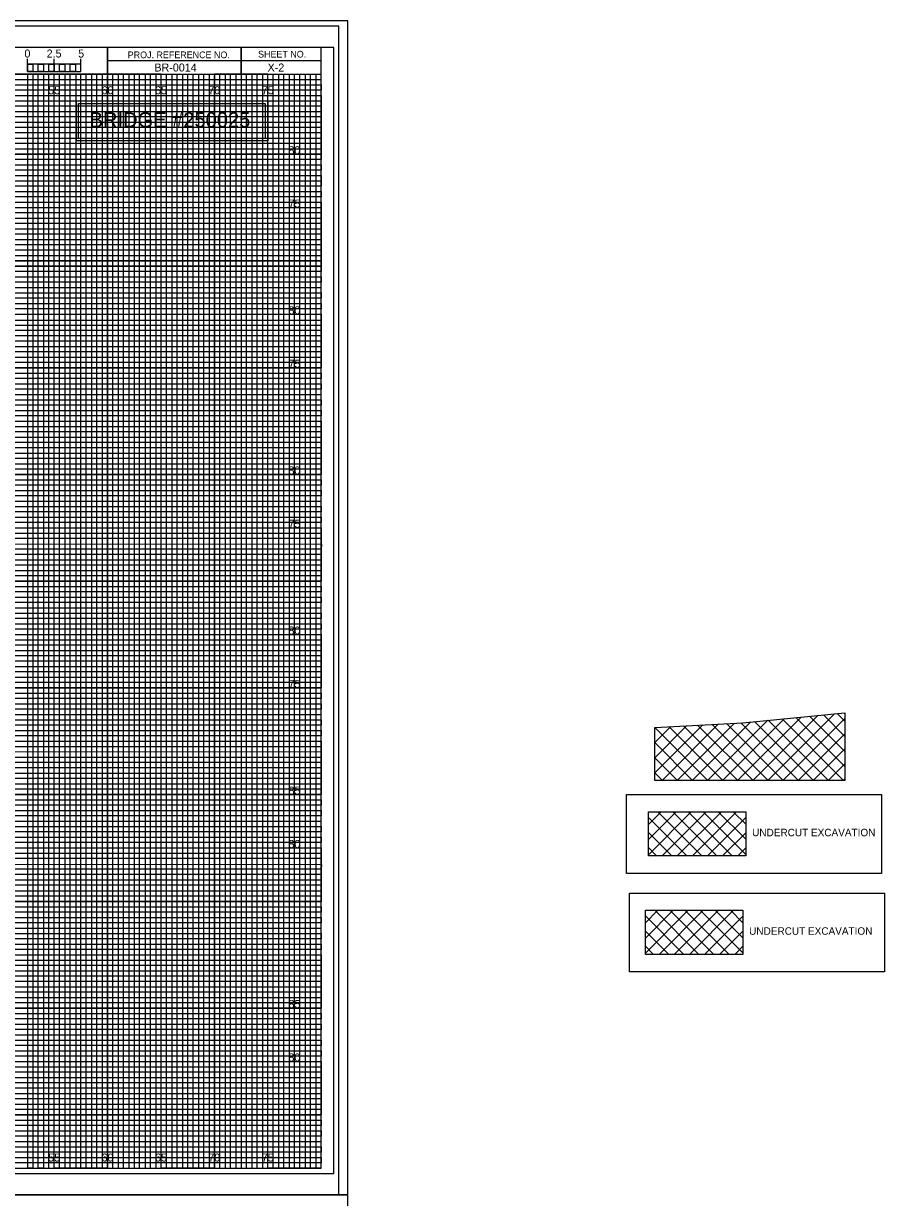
# Model space of a CAD drawing. Extents: x -8 to 533, y -20 to 768.
# Drawn here: x 132.1 to 212.8, y 107.2 to 217.2 of the extents above; entities that cross this region are included whole.
import ezdxf

# ---------------------------------------------------------------- set-up
doc = ezdxf.new("R2010")
doc.units = 0
for name, color, linetype in [('Old_Level_1', 7, 'Continuous'), ('Old_Level_34', 7, 'Continuous'), ('Prop Grid Mask', 7, 'Continuous'), ('Prop XS Bar Scale Labels', 7, 'Continuous'), ('Prop XS Elevation Labels', 7, 'Continuous'), ('Prop XS Offset Labels', 7, 'Continuous'), ('Prop XS Project Number', 7, 'Continuous'), ('Prop XS Sheet Number', 7, 'Continuous'), ('Prop XS Side Slope Text', 7, 'Continuous'), ('Prop XS Undercut Exc', 7, 'Continuous'), ('Sheet Cross Section CELL', 7, 'Continuous'), ('Sheet Cross Section Grid Major CELL', 7, 'Continuous'), ('Sheet Cross Section Grid Middle CELL', 7, 'Continuous'), ('Sheet Cross Section Grid Minor 1 CELL', 7, 'Continuous'), ('Sheet Cross Section Grid Minor 2 CELL', 7, 'Continuous'), ('Sheet Cross Section Scale CELL', 7, 'Continuous'), ('Sheet Cutting Line CELL', 7, 'Continuous'), ('Sheet DOT Grid CELL', 7, 'Continuous'), ('Sheet Plot Border Inside CELL', 7, 'Continuous'), ('Sheet Plot Border Outside CELL', 7, 'Continuous'), ('WEI Plot Border', 7, 'Continuous')]:
    doc.layers.add(name, color=color, linetype=linetype)

msp = doc.modelspace()

# ---------------------------------------------------------------- linework, layer by layer
at = {"layer": 'Old_Level_34'}
msp.add_lwpolyline([(137.26, 209.75), (154.74, 209.75), (154.74, 206.46), (137.26, 206.46)], close=True, dxfattribs=at)
at = {"layer": 'Prop Grid Mask'}
for points in [[(137.08, 210), (155, 210), (155, 206.24), (137.08, 206.24)], [(188.59, 145), (212.47, 145), (212.47, 137.61), (188.59, 137.61)], [(188.87, 135.78), (212.76, 135.78), (212.76, 128.39), (188.87, 128.39)]]:
    msp.add_lwpolyline(points, close=True, dxfattribs=at)
at = {"layer": 'Prop XS Undercut Exc'}
for p, q in [((194.76, 146.33), (200.25, 151.81)), ((196.18, 146.33), (201.82, 151.97)), ((197.59, 146.33), (203.38, 152.12)), ((199, 146.33), (204.95, 152.27)), ((200.42, 146.33), (206.52, 152.42)), ((200.58, 151.85), (206.11, 146.33)), ((201.83, 146.33), (208.08, 152.57)), ((201.87, 151.97), (207.52, 146.33)), ((203.16, 152.1), (208.93, 146.33)), ((203.25, 146.33), (209.05, 152.13)), ((204.45, 152.22), (209.05, 147.62)), ((205.74, 152.35), (209.05, 149.04)), ((207.03, 152.47), (209.05, 150.45)), ((208.32, 152.6), (209.05, 151.87)), ((191.24, 147.05), (195.73, 151.54)), ((191.24, 148.46), (194.23, 151.45)), ((191.24, 149.88), (192.74, 151.37)), ((191.24, 151.29), (196.21, 146.33)), ((191.93, 146.33), (197.22, 151.62)), ((192.58, 151.36), (197.62, 146.33)), ((193.35, 146.33), (198.72, 151.7)), ((193.92, 151.44), (199.03, 146.33)), ((195.26, 151.51), (200.45, 146.33)), ((196.61, 151.58), (201.86, 146.33)), ((197.95, 151.66), (203.28, 146.33)), ((199.29, 151.73), (204.69, 146.33)), ((204.66, 146.33), (209.05, 150.71)), ((191.24, 149.88), (194.79, 146.33)), ((206.08, 146.33), (209.05, 149.3)), ((191.24, 148.46), (193.38, 146.33)), ((207.49, 146.33), (209.05, 147.89)), ((191.24, 147.05), (191.96, 146.33)), ((208.9, 146.33), (209.05, 146.47)), ((190.64, 139.37), (194.65, 143.38)), ((190.64, 140.79), (193.24, 143.38)), ((190.64, 142.2), (191.83, 143.38)), ((191.53, 143.38), (195.66, 139.26)), ((191.94, 139.26), (196.07, 143.38)), ((192.94, 143.38), (197.07, 139.26)), ((193.35, 139.26), (197.48, 143.38)), ((194.36, 143.38), (198.49, 139.26)), ((194.77, 139.26), (198.9, 143.38)), ((195.77, 143.38), (199.76, 139.39)), ((197.19, 143.38), (199.76, 140.81)), ((198.6, 143.38), (199.76, 142.22)), ((190.64, 142.86), (194.24, 139.26)), ((196.18, 139.26), (199.76, 142.84)), ((190.64, 141.44), (192.83, 139.26)), ((197.6, 139.26), (199.76, 141.42)), ((190.64, 140.03), (191.42, 139.26)), ((199.01, 139.26), (199.76, 140.01)), ((190.36, 130.15), (194.37, 134.16)), ((190.36, 131.56), (192.96, 134.16)), ((190.36, 132.98), (191.54, 134.16)), ((190.36, 133.63), (193.96, 130.03)), ((191.25, 134.16), (195.37, 130.03)), ((191.66, 130.03), (195.79, 134.16)), ((192.66, 134.16), (196.79, 130.03)), ((193.07, 130.03), (197.2, 134.16)), ((194.07, 134.16), (198.2, 130.03)), ((194.49, 130.03), (198.61, 134.16)), ((195.49, 134.16), (199.48, 130.17)), ((195.9, 130.03), (199.48, 133.61)), ((196.9, 134.16), (199.48, 131.58)), ((198.32, 134.16), (199.48, 133)), ((190.36, 132.22), (192.55, 130.03)), ((197.31, 130.03), (199.48, 132.2)), ((190.36, 130.81), (191.13, 130.03)), ((198.73, 130.03), (199.48, 130.79))]:
    msp.add_line(p, q, dxfattribs=at)
for points in [[(209.05, 152.67), (209.05, 146.33), (191.24, 146.33), (191.24, 151.29), (199.48, 151.74)], [(190.64, 143.38), (199.76, 143.38), (199.76, 139.26), (190.64, 139.26)], [(190.36, 134.16), (199.48, 134.16), (199.48, 130.03), (190.36, 130.03)]]:
    msp.add_lwpolyline(points, close=True, dxfattribs=at)
at = {"layer": 'Sheet Cross Section CELL'}
for p, q in [((152.5, 215), (152.5, 212.5)), ((152.5, 212.5), (152.5, 215)), ((160, 213.75), (140, 213.75)), ((140, 213.75), (140, 212.5)), ((140, 212.5), (160, 212.5))]:
    msp.add_line(p, q, dxfattribs=at)
for points in [[(160, 215), (0, 215), (0, 110), (160, 110)], [(140, 215), (130, 215), (130, 212.52), (140, 212.52)], [(160, 215), (140, 215), (140, 212.5), (160, 212.5)]]:
    msp.add_lwpolyline(points, close=True, dxfattribs=at)
at = {"layer": 'Sheet Cross Section Grid Major CELL'}
for p, q in [((135, 110), (135, 212.5)), ((145, 212.5), (140, 212.5)), ((140, 212.5), (140, 110)), ((145, 110), (145, 212.5)), ((155, 212.5), (150, 212.5)), ((150, 212.5), (150, 110)), ((155, 110), (155, 212.5)), ((140, 110), (135, 110)), ((150, 110), (145, 110)), ((160, 110), (155, 110)), ((160, 110), (160, 110))]:
    msp.add_line(p, q, dxfattribs=at)
for points in [[(0, 210), (160, 210), (160, 205), (0, 205)], [(0, 200), (160, 200), (160, 195), (0, 195)], [(0, 190), (160, 190), (160, 185), (0, 185)], [(0, 180), (160, 180), (160, 175), (0, 175)], [(0, 170), (160, 170), (160, 165), (0, 165)], [(0, 160), (160, 160), (160, 155), (0, 155)], [(0, 150), (160, 150), (160, 145), (0, 145)], [(0, 140), (160, 140), (160, 135), (0, 135)], [(0, 130), (160, 130), (160, 125), (0, 125)], [(0, 120), (160, 120), (160, 115), (0, 115)]]:
    msp.add_lwpolyline(points, dxfattribs=at)
at = {"layer": 'Sheet Cross Section Grid Middle CELL'}
for points in [[(0, 212.5), (137.5, 212.5)], [(130, 212.5), (132.5, 212.5), (132.5, 110), (137.5, 110), (137.5, 212.5), (142.5, 212.5), (142.5, 110), (147.5, 110), (147.5, 212.5), (152.5, 212.5), (152.5, 110), (157.5, 110), (157.5, 212.5)], [(0, 202.5), (160, 202.5), (160, 207.5), (0, 207.5)], [(0, 192.5), (160, 192.5), (160, 197.5), (0, 197.5)], [(0, 182.5), (160, 182.5), (160, 187.5), (0, 187.5)], [(0, 172.5), (160, 172.5), (160, 177.5), (0, 177.5)], [(0, 162.5), (160, 162.5), (160, 167.5), (0, 167.5)], [(0, 152.5), (160, 152.5), (160, 157.5), (0, 157.5)], [(0, 142.5), (160, 142.5), (160, 147.5), (0, 147.5)], [(0, 132.5), (160, 132.5), (160, 137.5), (0, 137.5)], [(0, 122.5), (160, 122.5), (160, 127.5), (0, 127.5)], [(0, 112.5), (160, 112.5), (160, 117.5), (0, 117.5)]]:
    msp.add_lwpolyline(points, dxfattribs=at)
at = {"layer": 'Sheet Cross Section Grid Minor 1 CELL'}
msp.add_line((0, 212), (160, 212), dxfattribs=at)
for points in [[(0, 211.5), (135, 211.5), (160, 211.5), (160, 211), (0, 211)], [(0, 210.5), (160, 210.5), (160, 209.5), (0, 209.5)], [(0, 209), (160, 209), (160, 208.5), (0, 208.49)], [(0, 208), (160, 208), (160, 207), (0, 207)], [(0, 206.5), (160, 206.5), (160, 206), (0, 206)], [(0, 205.5), (160, 205.5), (160, 204.5), (0, 204.5)], [(0, 204), (160, 204), (160, 203.5), (0, 203.5)], [(0, 203), (160, 203), (160, 202), (0, 202)], [(0, 201.5), (160, 201.5), (160, 201), (0, 201)], [(0, 200.5), (160, 200.5), (160, 199.5), (0, 199.5)], [(0, 199), (160, 199), (160, 198.5), (0, 198.5)], [(0, 198), (160, 198), (160, 196.97), (160, 196.5), (160, 196), (0, 196)], [(0, 197), (160, 197), (160, 196.5), (0, 196.5)], [(0, 195.5), (160, 195.5), (160, 194.5), (0, 194.52)], [(0, 194.52), (160, 194.5), (160, 194), (0, 194)], [(0, 193.5), (160, 193.5), (160, 193), (0, 193)], [(0, 192), (160, 192), (160, 191.5), (0, 191.5)], [(0, 191), (160, 191), (160, 190.5), (0, 190.5)], [(-0.04, 189.44), (160, 189.44), (160, 188.94), (-0.04, 188.94)], [(0, 188.5), (160, 188.5), (160, 188), (0, 188)], [(0, 187), (160, 187), (160, 186.5), (0, 186.5)], [(0, 186), (160, 186), (160, 185.5), (0, 185.5)], [(0, 184.5), (160, 184.5), (160, 184), (0, 184)], [(0, 183.5), (160, 183.5), (160, 183), (0, 183)], [(0, 182), (160, 182), (160, 181.5), (0, 181.5)], [(0, 181), (160, 181), (160, 180.5), (0, 180.5)], [(0, 179.5), (160, 179.5), (160, 178.99), (0, 179)], [(0, 178.5), (160, 178.5), (160, 178), (0, 178)], [(0, 177), (160, 177), (160, 176.5), (0, 176.5)], [(0, 176), (160, 176), (160, 175.5), (0, 175.5)], [(0, 174.5), (160, 174.5), (160, 174), (0, 174)], [(0, 173.5), (160, 173.5), (160, 173), (0, 173)], [(0, 172), (160, 172), (160, 171.5), (0, 171.5)], [(0, 171), (160, 171), (160, 170.5), (0, 170.5)], [(0, 169.5), (160, 169.5), (160, 169), (0, 169)], [(0, 168.5), (160.03, 168.46), (160, 168), (0, 168)], [(0, 167), (160, 167), (160, 166.5), (0, 166.5)], [(0, 166), (160, 166), (160, 165.5), (0, 165.5)], [(0, 164.5), (160, 164.5), (160, 164), (0, 164)], [(0, 163.5), (160, 163.5), (160, 163), (0, 163)], [(0, 162), (160, 162), (160, 161.5), (0, 161.5)], [(0, 161), (160, 161), (160, 160.5), (0, 160.5)], [(0, 159.5), (160, 159.5), (160, 159), (0, 159)], [(0, 158.5), (160, 158.5), (160, 158), (0, 158)], [(0, 157), (160, 157), (160, 156.5), (0, 156.5)], [(0, 156), (160, 156), (160, 155.5), (0, 155.5)], [(0, 154.5), (160, 154.5), (160, 154), (0, 154)], [(0, 153.5), (160, 153.5), (160, 153), (0, 153)], [(0, 152), (160, 152), (160, 151.5), (0, 151.5)], [(0, 151), (160, 151), (160, 150.5), (0, 150.5)], [(0, 149.5), (160, 149.5), (160, 148.99), (0, 149)], [(0, 148.5), (160, 148.5), (160, 148), (0, 148)], [(0, 147), (160, 147), (160, 146.5), (0, 146.5)], [(0, 146), (160, 146), (160, 145.5), (0, 145.5)], [(0, 144.5), (160, 144.5), (160, 144), (0, 144)], [(0, 143.5), (160, 143.5), (160, 143), (0, 143)], [(0, 142), (160, 142), (160, 141.5), (0, 141.5)], [(0, 141), (160, 141), (160, 140.5), (0, 140.5)], [(0, 139.5), (160, 139.5), (160, 139), (0, 139)], [(0, 138.5), (160.03, 138.46), (160, 138), (0, 138)], [(0, 137), (160, 137), (160, 136.5), (0, 136.5)], [(0, 136), (160, 136), (160, 135.5), (0, 135.5)], [(0, 134.5), (160, 134.5), (160, 134), (0, 134)], [(0, 133.5), (160, 133.5), (160, 133), (0, 133)], [(0, 132), (160, 132), (160, 131.5), (0, 131.5)], [(0, 131), (160, 131), (160, 130.5), (0, 130.5)], [(0, 129.5), (160, 129.5), (160, 129), (0, 129)], [(0, 128.5), (160, 128.5), (160, 128), (0, 128)], [(0, 127), (160, 127), (160, 126.5), (0, 126.5)], [(0, 126), (160, 126), (160, 125.5), (0, 125.5)], [(0, 124.5), (160, 124.5), (160, 124), (0, 124)], [(0, 123.5), (160, 123.5), (160, 123), (0, 123)], [(0, 122), (160, 122), (160, 121.5), (0, 121.5)], [(0, 121), (160, 121), (160, 120.5), (0, 120.5)], [(0, 119.5), (160, 119.5), (160, 119), (0, 119)], [(0, 118.5), (160, 118.5), (160, 118), (0, 118)], [(0, 117), (160, 117), (160, 116.5), (0, 116.5)], [(0, 116), (160, 116), (160, 115.5), (0, 115.5)], [(0, 114.5), (160, 114.5), (160, 114), (0, 114)], [(0, 113.5), (160, 113.5), (160, 113), (0, 113)], [(0, 112), (160, 112), (160, 111.5), (0, 111.5)], [(0, 111), (160, 111), (160, 110.5), (0, 110.5)]]:
    msp.add_lwpolyline(points, dxfattribs=at)
at = {"layer": 'Sheet Cross Section Grid Minor 2 CELL'}
for p, q in [((133.5, 212.5), (133, 212.5)), ((133, 212.5), (133, 110)), ((133.5, 110), (133.5, 212.5)), ((134.5, 212.5), (134, 212.5)), ((134, 212.5), (134, 110)), ((134.5, 110), (134.5, 212.5)), ((133, 110), (132.5, 110)), ((134, 110), (133.5, 110))]:
    msp.add_line(p, q, dxfattribs=at)
for points in [[(135, 110), (135.49, 110), (135.49, 212.5), (136, 212.5), (136, 110)], [(136, 110), (136.5, 110), (136.5, 212.5), (137.03, 212.5), (137.03, 110)], [(137.5, 110), (138, 110), (138, 212.5), (138.5, 212.5), (138.5, 110)], [(138.5, 110), (139, 110), (139, 212.5), (139.5, 212.5), (139.5, 110)], [(140, 110), (140.5, 110), (140.5, 212.5), (141, 212.5), (141, 110)], [(141, 110), (141.5, 110), (141.5, 212.5), (142, 212.5), (142, 110)], [(142.5, 110), (143, 110), (143, 212.5), (143.5, 212.5), (143.5, 110)], [(143.5, 110), (144, 110), (144, 212.5), (144.5, 212.5), (144.5, 110)], [(145, 110), (145.5, 110), (145.5, 212.5), (146, 212.5), (146, 110)], [(146, 110), (146.5, 110), (146.5, 212.5), (147, 212.5), (147, 110)], [(147.5, 110), (148, 110), (148, 212.5), (148.5, 212.5), (148.5, 110)], [(148.5, 110), (149, 110), (149, 212.5), (149.5, 212.5), (149.5, 110)], [(150, 110), (150.5, 110), (150.5, 212.5), (151, 212.5), (151, 110)], [(151, 110), (151.5, 110), (151.5, 212.5), (152, 212.5), (152, 110)], [(152.5, 110), (153, 110), (153, 212.5), (153.5, 212.5), (153.5, 110)], [(153.5, 110), (154, 110), (154, 212.5), (154.5, 212.5), (154.5, 110)], [(155, 110), (155.5, 110), (155.5, 212.5), (156, 212.5), (156, 110)], [(156, 110), (156.5, 110), (156.5, 212.5), (157, 212.5), (157, 110)], [(157.5, 110), (158, 110), (158, 212.5), (158.5, 212.5), (158.5, 110)], [(158.5, 110), (159, 110), (159, 212.5), (159.5, 212.5), (159.5, 110)]]:
    msp.add_lwpolyline(points, dxfattribs=at)
at = {"layer": 'Sheet Cross Section Scale CELL'}
for p, q in [((132.5, 212.75), (132.5, 213.95)), ((132.5, 213.45), (132.5, 213.95)), ((135, 212.75), (135, 213.95)), ((137.5, 212.75), (137.5, 213.95)), ((137.5, 213.45), (137.5, 213.95))]:
    msp.add_line(p, q, dxfattribs=at)
for points in [[(137.5, 213.45), (132.5, 213.45), (132.5, 212.75), (137.5, 212.75)], [(132.5, 213.45), (133, 213.45), (133, 212.75), (132.5, 212.75)], [(133.5, 213.45), (134, 213.45), (134, 212.75), (133.5, 212.75)], [(134.5, 213.45), (135, 213.45), (135, 212.75), (134.5, 212.75)], [(135.5, 213.45), (136, 213.45), (136, 212.75), (135.5, 212.75)], [(136.5, 213.45), (137, 213.45), (137, 212.75), (136.5, 212.75)]]:
    msp.add_lwpolyline(points, close=True, dxfattribs=at)
at = {"layer": 'Sheet Cutting Line CELL'}
for p, q in [((161.65, 217), (-6.7, 217)), ((-6.7, 107.5), (161.65, 107.5))]:
    msp.add_line(p, q, dxfattribs=at)
at = {"layer": 'Sheet DOT Grid CELL'}
for p, q in [((135, 110), (135, 212.34)), ((140, 110), (140, 212.34)), ((145, 110), (145, 212.34)), ((150, 110), (150, 212.34)), ((155, 110), (155, 212.34)), ((0, 210), (160, 210)), ((0, 205), (160, 205)), ((0, 200), (160, 200)), ((0, 195), (160, 195)), ((0, 190), (160, 190)), ((0, 185), (160, 185)), ((0, 180), (160, 180)), ((0, 175), (160, 175)), ((0, 170), (160, 170)), ((0, 165), (160, 165)), ((0, 160), (160, 160)), ((0, 155), (160, 155)), ((0, 150), (160, 150)), ((0, 145), (160, 145)), ((0, 140), (160, 140)), ((0, 135), (160, 135)), ((0, 130), (160, 130)), ((0, 125), (160, 125)), ((0, 120), (160, 120)), ((0, 115), (160, 115))]:
    msp.add_line(p, q, dxfattribs=at)
at = {"layer": 'Sheet Plot Border Inside CELL'}
msp.add_lwpolyline([(-5.4, 109.5), (161.2, 109.5), (161.2, 215), (-5.4, 215)], close=True, dxfattribs=at)
at = {"layer": 'Sheet Plot Border Outside CELL'}
msp.add_lwpolyline([(-6.7, 107.5), (161.65, 107.5), (161.65, 217), (-6.7, 217)], close=True, dxfattribs=at)
at = {"layer": 'WEI Plot Border'}
for points in [[(-7.5, 107.5), (162.5, 107.5), (162.5, 217.5), (-7.5, 217.5)], [(-7.5, -2.5), (162.5, -2.5), (162.5, 107.5), (-7.5, 107.5)]]:
    msp.add_lwpolyline(points, close=True, dxfattribs=at)

# ---------------------------------------------------------------- texts
at = {"layer": 'Old_Level_1'}
msp.add_text('BRIDGE #250025', height=1.4062, rotation=360, dxfattribs=at).set_placement((138.31, 207.52))
at = {"layer": 'Prop XS Bar Scale Labels'}
for s, p in [('2.5', (134.29, 214.06)), ('5', (137.24, 214.06))]:
    msp.add_text(s, height=0.75, dxfattribs=at).set_placement(p)
at = {"layer": 'Prop XS Elevation Labels'}
for s, p in [('80', (156.93, 205)), ('75', (156.94, 200)), ('80', (156.93, 190)), ('75', (156.94, 185)), ('80', (156.93, 175)), ('75', (156.94, 170)), ('80', (156.93, 160)), ('75', (156.94, 155)), ('85', (156.94, 145)), ('80', (156.93, 140)), ('85', (156.94, 125)), ('80', (156.93, 120))]:
    msp.add_text(s, height=0.75, dxfattribs=at).set_placement(p)
at = {"layer": 'Prop XS Offset Labels'}
for s, p in [('55', (134.44, 210.62)), ('60', (139.43, 210.62)), ('65', (144.44, 210.62)), ('70', (149.43, 210.62)), ('75', (154.44, 210.62)), ('55', (134.44, 110.62)), ('60', (139.43, 110.62)), ('65', (144.44, 110.62)), ('70', (149.43, 110.62)), ('75', (154.44, 110.62))]:
    msp.add_text(s, height=0.75, dxfattribs=at).set_placement(p)
at = {"layer": 'Prop XS Project Number'}
msp.add_text('BR-0014', height=0.75, dxfattribs=at).set_placement((144.38, 212.75))
at = {"layer": 'Prop XS Sheet Number'}
msp.add_text('X-2', height=0.75, dxfattribs=at).set_placement((154.98, 212.75))
at = {"layer": 'Prop XS Side Slope Text'}
for p in [(200.36, 141.1), (200.08, 131.87)]:
    msp.add_text('UNDERCUT EXCAVATION', height=0.7, dxfattribs=at).set_placement(p)
at = {"layer": 'Sheet Cross Section CELL'}
for s, p in [('PROJ. REFERENCE NO.', (141.88, 214)), ('SHEET NO.', (154.09, 214.06))]:
    msp.add_text(s, height=0.625, dxfattribs=at).set_placement(p)
at = {"layer": 'Sheet Cross Section Scale CELL'}
msp.add_text('0', height=0.75, dxfattribs=at).set_placement((132.21, 214.06))

doc.saveas('drawing.dxf')
